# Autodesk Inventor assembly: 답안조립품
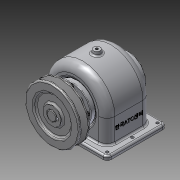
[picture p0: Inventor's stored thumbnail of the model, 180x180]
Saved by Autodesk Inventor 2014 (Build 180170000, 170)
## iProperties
Created: 2015-09
Part Number: 답안조립품
Document SubType Name: Assembly
Designer: Administrator
Author: Administrator
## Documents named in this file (14)
- C:\Users\Administrator\Desktop\450907V1047\답안조립품.iam
- C:\Users\Administrator\Desktop\450907V1047\1-본체.ipt
- C:\Users\Administrator\Desktop\450907V1047\V-벨트풀리.ipt
- C:\Users\Administrator\Desktop\450907V1047\뒤커버.ipt
- C:\Users\Administrator\Desktop\450907V1047\멈춤나사 - M4x10.ipt
- C:\Users\Administrator\Desktop\450907V1047\베어링 6203.ipt
- C:\Users\Administrator\Desktop\450907V1047\볼트 M3 x 8.ipt
- C:\Users\Administrator\Desktop\450907V1047\볼트 M3 x 10.ipt
- C:\Users\Administrator\Desktop\450907V1047\스퍼기어.ipt
- C:\Users\Administrator\Desktop\450907V1047\앞커버.ipt
- C:\Users\Administrator\Desktop\450907V1047\오일 실 17 32 8.ipt
- C:\Users\Administrator\Desktop\450907V1047\축.ipt
- C:\Users\Administrator\Desktop\450907V1047\키 - 5 x 5 x 18.ipt
- C:\Users\Administrator\Desktop\450907V1047\키 - 6 x 6 x 22.ipt
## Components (10 placed, 4 different names)
1. 1-본체:1 — 플러쉬:1, 플러쉬:2
2. V-벨트풀리:1
3. ISO 4762 M3 x 8:1
4. ISO 4762 M3 x 8:2
5. ISO 4762 M3 x 8:3
6. ISO 4762 M3 x 8:4
7. ISO 4762 M3 x 10:1
8. ISO 4762 M3 x 10:2
9. ISO 4762 M3 x 10:3
10. ISO 4762 M3 x 10:4
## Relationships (2: Flush 2)
- 플러쉬:1 [Flush]: 1-본체:1
- 플러쉬:2 [Flush]: 1-본체:1
